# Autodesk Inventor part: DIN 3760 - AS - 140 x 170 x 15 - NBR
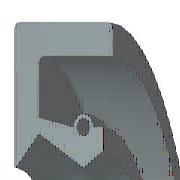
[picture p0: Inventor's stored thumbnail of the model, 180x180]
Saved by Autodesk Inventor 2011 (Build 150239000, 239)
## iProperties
Created: 2010-02
Part Number: DIN 3760 - AS - 140 x 170 x 15 - NBR
Material: Rubber
Description: Shaft Seal Ring
Document SubType Name: Modeling
Standard: DIN 3760
Designer: 129877
Standards Organization: DIN
Language: en-US
Size Designation: AS - 140 x 170 x 15 - NBR
Categories: <MemberInstance><Categories><Category DisplayName="Shaft Parts" InternalName="7f7aeb1f-a693-4053-b835-cee3144e0d98" Mnemonic="SHFT"><Category DisplayName="Seali
Density: 0.93 g/cm^3
Mass: 57.984 g
Surface Area: 392.668 cm^2
Volume: 62.3484 cm^3
IsCustomPart: 0
Author: 129877
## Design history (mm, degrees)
revolve "Body" stored, may be unused: angle "d17" = 90 deg
revolve "Spring1" stored, may be unused: angle "d18" = 90 deg
body "Solid1"
sketch "Sketch1"
  geometry: L1 (0, 85)-(15, 85); L2 (15, 81.25)-(3.75, 81.25); L3 (3.75, 73.75)-(10.5, 70); L4 (10.5, 70)-(0, 70); L5 (0, 0)-(9.586, 0) reference; L6 (10.5, 70)-(13.5, 71.875); L7 (0, 18)-(0, -3) reference; L8 (-1.941, 0)-(11.507, 0) reference; L9 (9, 74.5)-(3.75, 75.55); L10 (3.75, 75.55)-(3.75, 81.25); L11 (0, 85)-(0, 70.188); L12 (10.5, 70)-(0, 70); L13 (3.75, 73.75)-(0.325, 70.06); L14 (15, 85)-(15, 81.25); L15 (12, 74.5)-(13.5, 74.5); L16 (13.5, 74.5)-(13.5, 71.875); C1 r 0.975 at (10.5, 74.5); A1 r 1.5 centre (10.5, 74.5) between (12, 74.5) and (9, 74.5); A2 r 0.188 centre (0.187, 70.188) between (0, 70.188) and (0.325, 70.06); 1 further point
  constraints: 28 end point, 5 horizontal alignment, 5 point on line, 4 point on circle, 4 vertical alignment, 3 centre point, 3 tangent, 2 collinear, 2 horizontal, 2 perpendicular, 1 coincident, 1 parallel
  dimensions: "d0" = 170 diameter of L1 L5 (= SD2); "d1" = 3.75 distance of L1.end L2.start (= SD); "d2" = 1.95 diameter of C1 (= SPDI); "d3" = 3 diameter of A1 (= SPDA); "d4" = 140 diameter of L3.end L5 (= NND); "d5" = 147.5 diameter of L3.start L5 (= TKDM); "d7" = 151.1 diameter of L9.end L5 (= TKDM + 0.24 x SWDT); "d8" = 3.75 distance between parallel lines of L11 L10 (= SD); "d9" = 10.5 distance from line of L11 C1.centre (= SPDST); "d10" = 149 diameter of C1.centre L5 (= HLDM); "d11" = 0.1875 radius of A2 (= 0.25 x LAB); "d12" = 13.5 distance between parallel lines of L11 L16 (= SDI); "d13" = 143.75 diameter of L6.end L5 (= ABDM); "d14" = 15 distance from line of L11 L1.end (= SWDT)
fillet "Fillet1" dims "d6" = 1 (= RR)
other parameters: "SD2" = 170 [user parameter; used in 1 equation term], "SWDT" = 15 [user parameter; used in 2 equation terms], "RR" = 1 [user parameter; used in 1 equation term], "SD" = 3.75 [user parameter; used in 2 equation terms], "NND" = 140 [user parameter; used in 1 equation term], "SPDA" = 3 [user parameter; used in 1 equation term], "SPDI" = 1.95 [user parameter; used in 1 equation term], "TKDM" = 147.5 [user parameter; used in 2 equation terms], "HLDM" = 149 [user parameter; used in 1 equation term], "ABDM" = 143.75 [user parameter; used in 1 equation term], "SDI" = 13.5 [user parameter; used in 1 equation term], "SPDST" = 10.5 [user parameter; used in 1 equation term], "LAB" = 0.75 [user parameter; used in 1 equation term], "d15" = 0, "d16" = 0, "d19" = 0
